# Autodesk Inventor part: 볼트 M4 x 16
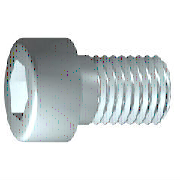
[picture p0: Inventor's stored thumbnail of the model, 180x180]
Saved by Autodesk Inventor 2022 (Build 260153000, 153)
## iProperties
IsCustomPart: 0
Created: 2012-02
Part Number: 볼트 M4 x 16
Material: 스테인리스강
Description: 6각 소켓 머리 캡 나사
Document SubType Name: Modeling
Standard: ISO 4762
Designer: mduedu
Standard Revision: Fourth edition 2004-03-01
Standards Organization: ISO
Language: ko-KR
Size Designation: M4 x 16
Categories: <MemberInstance><Categories><Category DisplayName="조임쇠" InternalName="e4da775c-781d-43d5-af7c-5136215cf5a6" Mnemonic="FSTN"><Category DisplayName="볼트" InternalN
Density: 7.75 g/cm^3
Appearance: 반광택
Author: mduedu
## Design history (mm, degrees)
sketch "스케치1"
  geometry: L1 (-1, 0)-(16, 0); L2 (16, 0)-(16, 2); L3 (16, 2)-(1.75, 2); L4 (1.75, 2)-(1.32, 2); L5 (1.32, 2)-(0, 2); L6 (0, 2)-(0, 3.5); L7 (0, 3.5)-(-4, 3.5); L8 (-4, 3.5)-(-4, 1.732); L9 (-4, 1.732)-(-2, 1.732); L10 (-2, 1.732)-(-1, 0); L11 (-8, 0)-(20, 0) reference; L12 (0, -0.7)-(0, 4.2) reference; L13 (1.75, 2)-(0, 2)
  constraints: 22 end point, 6 parallel, 2 collinear, 2 perpendicular, 1 horizontal, 1 point on line
  dimensions: "d1" = 14.25 distance from line of L3.end L2 (= GEL); "d2" = 0.42952 distance of L4.end L3.end (computed from GAL); "d3" = 4 distance between parallel lines of L8 L6 (= KOH); "d4" = 2 distance of L8.end L9.end (= INTI); "d5" = 60 deg angle of L10 L1; "d6" = 4 diameter of L3 L1 (= GD); "d7" = 4 diameter of L5 L1 (= BDM); "d8" = 3.4641 diameter of L9 L1 (= 1.1547 x SW); "d9" = 7 diameter of L7 L1 (= KOD); "d26" = 16 distance between parallel lines of L12 L2 (= NLG)
revolve "본체" sketch "스케치1" stored, may be unused: angle "d10" = 90 deg
sketch "스케치2"
  geometry: L1 (0, -4.9)-(0, 4.9) reference; L2 (-4.9, 0)-(4.9, 0) reference; L3 (1.732, 0)-(0.866, -1.5); L4 (0.866, -1.5)-(-0.866, -1.5); L5 (-0.866, -1.5)-(-1.732, 0); L6 (-1.732, 0)-(-0.866, 1.5); L7 (-0.866, 1.5)-(0.866, 1.5); L8 (0.866, 1.5)-(1.732, 0); 2 further points
  constraints: 12 end point, 1 coincident, 1 horizontal alignment, 1 point on line, 12 other
extrude "슬롯" join sketch "스케치2" stored distance "d11" = 10; taper "d12" = 0 deg
workplane "Work Plane1"
fillet "Fillet2" dims "d30" = 0.1 (= R)
body "Solid1"
fillet "모깎기1" dims "d17" = 0.4 (= RR)
feature "스레드" dims "d13" = 14.25 (= GEL), "d14" = 0
chamfer "모따기1" distance "d15" = 0.42941 (= -0.5 x SPD + 0.5 x GD); stored, may be unused: second distance "d16" = 0.42941 (= GUL), angle "d27" = 45 deg
other parameters: "GD" = 4 [user parameter; used in 2 equation terms], "NLG" = 16 [user parameter; used in 1 equation term], "GEL" = 14.25 [user parameter; used in 2 equation terms], "KOD" = 7 [user parameter; used in 1 equation term], "KOH" = 4 [user parameter; used in 1 equation term], "INTI" = 2 [user parameter; used in 1 equation term], "GAL" = 0.42941 (= 0.61345 x PTC) [user parameter; used in 1 equation term], "GUL" = 0.42941 (= 0.61345 x PTC) [user parameter; used in 1 equation term], "BDM" = 4 (= NND) [user parameter; used in 1 equation term], "SW" = 3 [user parameter; used in 2 equation terms], "RR" = 0.4 [user parameter; used in 1 equation term], "SPD" = 3.14117 (= NND - 1.2269 x PTC) [user parameter; used in 1 equation term], "d19" = 0, "d28" = 0, "d29" = 0, "R" = 0.1 [user parameter; used in 1 equation term], "TOA" = 30 deg [user parameter], "GD1" = 3.14117 (= THREADDIA - 1.2269 x PTC) [user parameter], "THREADDIA" = 4 [user parameter; used in 1 equation term], "FAWI" = 45 deg [user parameter], "TPU" = 14.28571 (computed from PTC) [user parameter], "PTC" = 0.7 [user parameter; used in 5 equation terms], "NND" = 4 [user parameter; used in 2 equation terms], "E0" = 3.465 (= 1.155 x SW) [user parameter]
